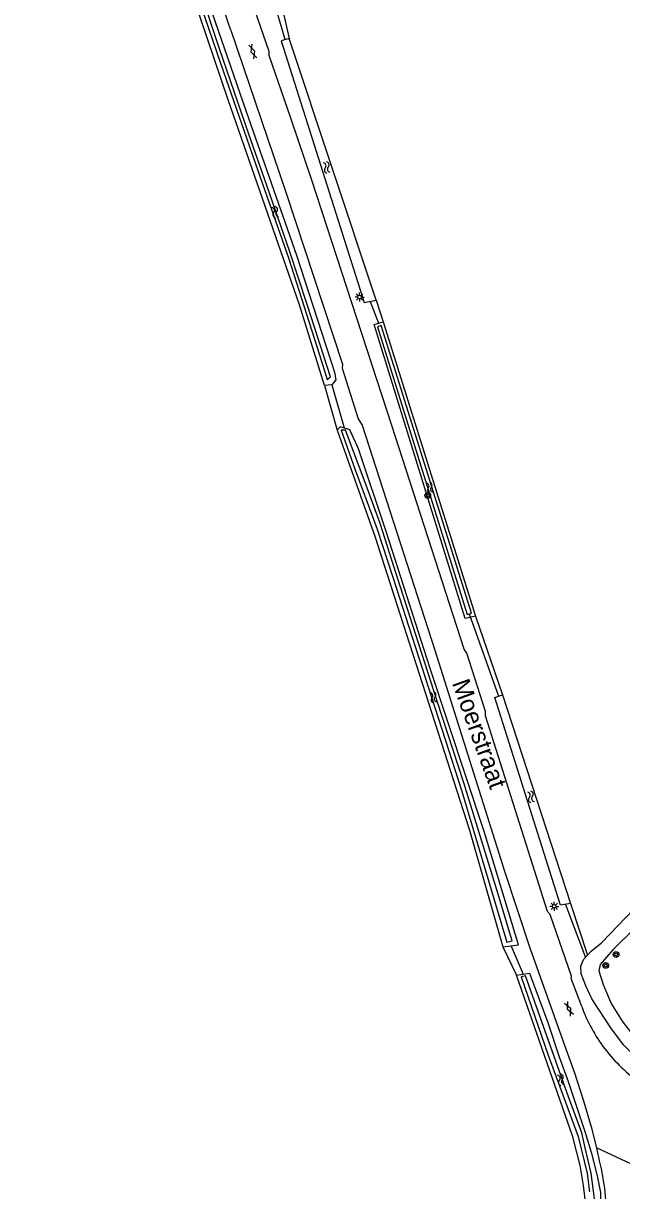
# Model space of a CAD drawing. Extents: x 133000 to 136000, y 400500 to 403500.
# Drawn here: x 134460 to 134543.9, y 400652.6 to 400816 of the extents above; entities that cross this region are included whole.
import ezdxf

# ---------------------------------------------------------------- set-up
doc = ezdxf.new("R2010")
doc.units = 0
for name, color, linetype in [('gg-anno-openbare ruimte label', 7, 'Continuous'), ('gg-knt-verharding', 7, 'Continuous'), ('gg-kntw-bovenkant insteek waterloop', 7, 'Continuous'), ('gg-kntw-waterlijn', 7, 'Continuous'), ('gg-kwrk-duiker nz buis', 7, 'Continuous'), ('gt-grn-groengrens', 7, 'Continuous'), ('gt-grn-weggrens', 7, 'Continuous'), ('gt-symb-boom', 7, 'Continuous'), ('gt-symb-gesloten verharding', 7, 'Continuous'), ('gt-symb-lichtmast', 7, 'Continuous'), ('gt-symb-watersymbool', 7, 'Continuous')]:
    doc.layers.add(name, color=color, linetype=linetype)

# ---------------------------------------------------------------- blocks, each defined once
blk = doc.blocks.new('gt0-WA')
at = {"layer": 'gt-symb-watersymbool'}
for centre, start, end in [((-0.32, 0.02), 28.0725, 151.9275), ((0.43, 0.42), 208.0725, 331.9275), ((-0.32, -0.43), 28.0725, 151.9275), ((0.43, -0.03), 208.0725, 331.9275)]:
    blk.add_arc(centre, 0.425, start, end, dxfattribs=at)
blk = doc.blocks.new('gt0-GESVH1')
at = {"layer": 'gt-symb-gesloten verharding'}
for p, q in [((-0.99, -0.26), (0.01, 0.24)), ((0.01, -0.26), (-0.99, 0.24)), ((0.01, 0.24), (1.01, -0.26)), ((1.01, 0.24), (0.01, -0.26))]:
    blk.add_line(p, q, dxfattribs=at)
blk = doc.blocks.new('gt0-LMAST')
at = {"layer": 'gt-symb-lichtmast'}
for p, q in [((-0.18, 0.17), (-0.45, 0.44)), ((-0.01, 0.25), (-0.01, 0.62)), ((0.17, 0.17), (0.44, 0.44)), ((-0.26, 0), (-0.63, 0)), ((-0.18, -0.18), (-0.45, -0.45)), ((-0.01, -0.25), (-0.01, -0.63)), ((0.44, -0.45), (0.17, -0.18)), ((0.24, 0), (0.62, 0))]:
    blk.add_line(p, q, dxfattribs=at)
blk.add_circle((-0.01, 0), 0.25, dxfattribs=at)
blk = doc.blocks.new('gt0-BOOM')
at = {"layer": 'gt-symb-boom'}
for radius in [0.4, 0.2]:
    blk.add_circle((0, 0), radius, dxfattribs=at)

msp = doc.modelspace()

# ---------------------------------------------------------------- linework, layer by layer
at = {"layer": 'gg-knt-verharding'}
msp.add_line((134540.32, 400658.54), (134540.49, 400657.81), dxfattribs=at)
for points in [[(134538.26, 400678.33), (134536.79, 400682.25), (134536.83, 400682.58), (134533.82, 400691.22), (134533.48, 400691.63), (134524.77, 400719.04), (134524.76, 400719.62), (134522.17, 400727.8), (134521.81, 400728.37), (134511.68, 400759.69), (134500.49, 400793.89), (134497.52, 400802.69), (134494.49, 400811.47), (134494.48, 400812.04), (134491.58, 400820.44), (134491.19, 400820.91)], [(134489.11, 400815), (134496.79, 400792.36), (134504.75, 400768.26), (134504.71, 400767.69), (134506.96, 400760.61), (134507.51, 400759.7), (134517.67, 400728.23), (134527.46, 400697.3), (134530.97, 400686.55), (134535.84, 400672.91), (134537.25, 400669.04), (134538.53, 400665.13), (134539.6, 400661.49), (134540.32, 400658.54)]]:
    msp.add_lwpolyline(points, dxfattribs=at)
for centre, radius, start, end in [((134216.5, 400726.06), 286.75, 18.068, 21.7818), ((134559.89, 400686.29), 23.05, 200.1997, 217.0144), ((134564.81, 400691.13), 29.91, 218.738, 232.1767), ((134504.2, 400648.02), 37.59, 1.4845, 15.0923)]:
    msp.add_arc(centre, radius, start, end, dxfattribs=at)
at = {"layer": 'gg-kntw-bovenkant insteek waterloop'}
for p, q in [((134509.46, 400777.21), (134497.27, 400813.87)), ((134510.44, 400774.17), (134523.39, 400732.99)), ((134527.16, 400721.95), (134536.7, 400692.76))]:
    msp.add_line(p, q, dxfattribs=at)
for points in [[(134460.04, 400869.08), (134460.23, 400870.18), (134461, 400870.65), (134462.13, 400869.95), (134465.54, 400864), (134469.96, 400856.71), (134473.61, 400850.4), (134476.89, 400843.5), (134479.7, 400836.38), (134485.15, 400821.38), (134491.25, 400803.65), (134498.3, 400783.53), (134503.65, 400767.13), (134503.8, 400766.07), (134503.27, 400765.39), (134502.21, 400765.28)], [(134502.21, 400765.28), (134498.72, 400776.55), (134488.71, 400805.25), (134482.9, 400822.52), (134479.38, 400832.18), (134476.47, 400839.41), (134472.78, 400847.23), (134467.88, 400856.24), (134460.04, 400869.08)], [(134497.27, 400813.87), (134496.16, 400813.52), (134507.8, 400776.88), (134509.46, 400777.21)], [(134523.39, 400732.99), (134521.95, 400732.66), (134509.18, 400773.82), (134510.44, 400774.17)], [(134527.23, 400686.68), (134529.4, 400686.99), (134524.58, 400702.82), (134517.04, 400725.66), (134510.9, 400744.7), (134506.97, 400756.43), (134505.77, 400759.08), (134504.44, 400759.49), (134504.02, 400759)], [(134504.02, 400759), (134509.28, 400744.16), (134522.54, 400703.05), (134527.23, 400686.68)], [(134536.7, 400692.76), (134535.28, 400692.52), (134526.08, 400721.6), (134527.16, 400721.95)], [(134539.07, 400685.51), (134539.58, 400686.08), (134541.03, 400687.27), (134545.58, 400691.95), (134550.46, 400697.36), (134555.15, 400701.78), (134557.19, 400704.05), (134558.59, 400705.15), (134560.18, 400706.18)], [(134560.18, 400706.18), (134561.4, 400706.43), (134562.13, 400706.1), (134561.66, 400705.62), (134560.56, 400704.36), (134554.96, 400698.43), (134542.6, 400686.26), (134540.86, 400684.23), (134540.67, 400683.33), (134541.25, 400681.41), (134542.39, 400678.75), (134543.94, 400676.29), (134545.8, 400673.86), (134547.81, 400671.67), (134550.14, 400669.77), (134556.92, 400665.14), (134563.77, 400661.11), (134572.83, 400656.08)], [(134572.76, 400655.48), (134571.84, 400655.12), (134570.11, 400655.69), (134560, 400660.91), (134554.58, 400664.43), (134548.4, 400668.89), (134546.28, 400670.83), (134544.16, 400672.92), (134542.45, 400675.24), (134539.66, 400679.41), (134538.84, 400681.25), (134538.2, 400682.93), (134538.15, 400683.98), (134538.53, 400684.92), (134539.07, 400685.51)], [(134529.13, 400682.74), (134530.94, 400683.02), (134533.52, 400676.11), (134535.08, 400671.28), (134536.34, 400667.83), (134538.76, 400660.72), (134539.59, 400657.93), (134540.41, 400654.64), (134540.87, 400652.32), (134540.9, 400649.51), (134540.76, 400647.26), (134540.32, 400645.02), (134539.37, 400642.46), (134533.73, 400629.46), (134521.65, 400600.9)], [(134518.52, 400598.55), (134519.77, 400601.47), (134527.21, 400619.31), (134533.16, 400632.59), (134536.07, 400638.98), (134537.54, 400643.18), (134538.24, 400645.66), (134538.79, 400647.89), (134538.85, 400650.59), (134538.51, 400653.31), (134538.02, 400656.09), (134537.03, 400660.08), (134529.13, 400682.74)]]:
    msp.add_lwpolyline(points, dxfattribs=at)
at = {"layer": 'gg-kntw-waterlijn'}
for points in [[(134482.55, 400825.27), (134487.64, 400810.4), (134493.22, 400794.42), (134497.17, 400783.16), (134501.52, 400769.58), (134502.62, 400766.1), (134503.06, 400766.5), (134499.84, 400776.45), (134497.34, 400784.12), (134493.77, 400794.35), (134491.61, 400800.45), (134487.52, 400812.4), (134484.78, 400820.76)], [(134522.2, 400733.21), (134522.83, 400733.4), (134510.18, 400773.66), (134509.63, 400773.5), (134522.2, 400733.21)], [(134504.56, 400759.01), (134506.52, 400753.48), (134509.62, 400745.14), (134511.74, 400738.58), (134521.42, 400708.64), (134527.79, 400687.33), (134528.51, 400687.55), (134526.38, 400694.69), (134521.74, 400709.66), (134517.99, 400721.08), (134512.05, 400739.65), (134510.04, 400745.94), (134508.04, 400751.34), (134505.19, 400759.04), (134504.56, 400759.01)], [(134540.03, 400651.41), (134539.57, 400655.02), (134538.75, 400658.56), (134538.27, 400660.64), (134536.41, 400665.72), (134530.39, 400682.64), (134529.78, 400682.52)], [(134529.78, 400682.52), (134533.57, 400671.53), (134537.74, 400660.13), (134539, 400654.97), (134539.36, 400652.38)]]:
    msp.add_lwpolyline(points, dxfattribs=at)
at = {"layer": 'gg-kwrk-duiker nz buis'}
for p, q in [((134496.72, 400813.69), (134494.64, 400820.86)), ((134508.63, 400777.05), (134509.81, 400774.02)), ((134503.27, 400765.39), (134504.96, 400759.33)), ((134522.47, 400733.32), (134526.62, 400721.78)), ((134535.99, 400692.64), (134538.77, 400685.18)), ((134528.37, 400686.81), (134530.04, 400682.88))]:
    msp.add_line(p, q, dxfattribs=at)
at = {"layer": 'gt-grn-groengrens'}
for p, q in [((134495.61, 400821.24), (134497.27, 400813.87)), ((134509.46, 400777.21), (134510.44, 400774.17)), ((134502.21, 400765.28), (134504.02, 400759)), ((134523.39, 400732.99), (134527.16, 400721.95)), ((134536.7, 400692.76), (134539.07, 400685.51)), ((134527.23, 400686.68), (134529.13, 400682.74))]:
    msp.add_line(p, q, dxfattribs=at)
at = {"layer": 'gt-grn-weggrens'}
msp.add_lwpolyline([(134551.34, 400653.24), (134550.36, 400653.82), (134548.22, 400654.8), (134546.25, 400655.79), (134544.54, 400656.6), (134541.75, 400657.89), (134540.32, 400658.54)], dxfattribs=at)

# ---------------------------------------------------------------- block references
at = {"layer": 'gt-symb-boom'}
for p in [(134516.69, 400749.87), (134543.07, 400685.61), (134541.62, 400684.1)]:
    msp.add_blockref('gt0-BOOM', p, dxfattribs=at)
at = {"layer": 'gt-symb-gesloten verharding'}
for p, rotation in [((134492.2, 400812.04), -71.45633066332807), ((134536.48, 400678.03), -66.1771005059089)]:
    msp.add_blockref('gt0-GESVH1', p, dxfattribs=dict(at, rotation=rotation))
at = {"layer": 'gt-symb-lichtmast'}
for p in [(134507.14, 400777.65), (134534.42, 400692.36)]:
    msp.add_blockref('gt0-LMAST', p, dxfattribs=at)
at = {"layer": 'gt-symb-watersymbool'}
for p, rotation in [((134502.53, 400795.85), -71.9999254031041), ((134495.31, 400789.58), -71.58316555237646), ((134516.95, 400751.03), -71.9999254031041), ((134517.48, 400721.69), -71.9999254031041), ((134531.12, 400707.74), -71.9999254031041), ((134535.32, 400668.13), -71.9999254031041)]:
    msp.add_blockref('gt0-WA', p, dxfattribs=dict(at, rotation=rotation))

# ---------------------------------------------------------------- texts
at = {"layer": 'gg-anno-openbare ruimte label'}
msp.add_text('Moerstraat', height=2.5, rotation=289.8, dxfattribs=at).set_placement((134520.06, 400723.63))

doc.saveas('drawing.dxf')
